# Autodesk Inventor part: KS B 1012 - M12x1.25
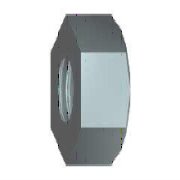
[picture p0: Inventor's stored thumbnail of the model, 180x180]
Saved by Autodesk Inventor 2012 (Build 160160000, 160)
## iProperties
IsCustomPart: 0
Created: 2009-02
Part Number: KS B 1012 - M12x1.25
Material: 강, 연강
Description: 6각 너트
Document SubType Name: Modeling
Standard: KS B 1012
Designer: KYOUNG IL JANG
Standards Organization: KS
Language: ko-KR
Size Designation: M12x1.25
Categories: <MemberInstance><Categories><Category DisplayName="조임쇠" InternalName="e4da775c-781d-43d5-af7c-5136215cf5a6" Mnemonic="FSTN"><Category DisplayName="너트" InternalN
Density: 1 g/cm^3
Author: KYOUNG IL JANG
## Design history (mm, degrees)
body "Solid1"
sketch "스케치1"
  geometry: L1 (10.97, 0)-(5.485, -9.5); L2 (5.485, -9.5)-(-5.485, -9.5); L3 (-5.485, -9.5)-(-10.97, 0); L4 (-10.97, 0)-(-5.485, 9.5); L5 (-5.485, 9.5)-(5.485, 9.5); L6 (5.485, 9.5)-(10.97, 0); 2 further points
  constraints: 12 end point, 1 coincident, 1 horizontal, 11 other
  dimensions: "d0" = 21.93931 distance of L1.start L3.end (= 1.1547 x SW)
extrude "본체" new body sketch "스케치1" distance "d1" = 10 (= KOH); taper "d2" = 0 deg
revolve "모따기3" stored, may be unused: angle "d5" = 90 deg
sketch "스케치2"
  geometry: 1 further point
hole "스레드" sketch "스케치2" diameter "d6" = 10.647; stored, may be unused: countersink angle "d10" = 82 deg, drill point angle "d12" = 118 deg; dims "d7" = 12.7, "d8" = 9.525, "d9" = 6.35, "d11" = 19.05
workaxis "Work Axis1"
workplane "Work Plane1"
chamfer "모따기1" distance "d13" = 0.67658 (= -0.5 x GD1 + 0.5 x NND); stored, may be unused: angle "d14" = 30 deg, second distance "d21" = 0.67658 (= -0.5 x GD1 + 0.5 x NND)
chamfer "모따기2" distance "d15" = 0.67658 (= -0.5 x GD1 + 0.5 x NND); stored, may be unused: angle "d16" = 30 deg, second distance "d22" = 0.67658 (= -0.5 x GD1 + 0.5 x NND)
sketch "스케치3"
  geometry: L1 (0, 10.97)-(10, 10.97) reference; L2 (10, 5.485)-(10, 10.97) reference; L3 (-2, 0)-(12, 0) reference; L4 (9.151, 10.97)-(10, 9.5)
  constraints: 2 end point, 2 point on line
  dimensions: "d3" = 19 diameter of L4.end L3 (= SW01); "d4" = 30 deg angle of L2 L4 (= ANG2)
other parameters: "ANG2" = 30 deg [user parameter; used in 1 equation term], "NND" = 12 [user parameter; used in 4 equation terms], "KOH" = 10 [user parameter; used in 1 equation term], "SW" = 19 [user parameter; used in 3 equation terms], "SW01" = 19 (= SW) [user parameter; used in 1 equation term], "GD1" = 10.64684 (computed from THREADDIA, PTC, TOA) [user parameter; used in 4 equation terms], "d19" = 0, "d20" = 0, "d24" = 0, "d25" = 0, "GUL" = 0.67658 (= 0.541266 x PTC) [user parameter], "TPU" = 8 (computed from PTC) [user parameter], "TOA" = 30 deg [user parameter; used in 1 equation term], "PTC" = 1.25 [user parameter; used in 4 equation terms], "E0" = 21.945 (= 1.155 x SW) [user parameter], "THREADDIA" = 12 [user parameter; used in 1 equation term], "GAL" = 0.67658 (= 0.541266 x PTC) [user parameter]
